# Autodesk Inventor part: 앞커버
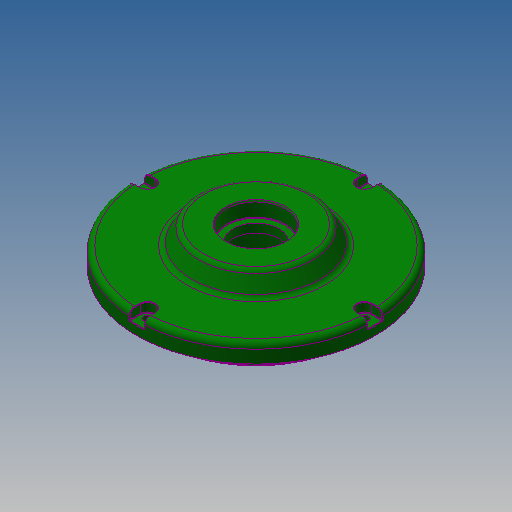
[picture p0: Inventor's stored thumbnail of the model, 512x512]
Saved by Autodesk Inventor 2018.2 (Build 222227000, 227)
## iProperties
Created: 2016-11
Part Number: 앞커버
Material: 알루미늄 6061
Document SubType Name: Modeling
Designer: mduedu
Density: 2.71 g/cm^3
Mass: 470.684 g
Surface Area: 413.208 cm^2
Volume: 173.684 cm^3
Appearance: 진녹색
Author: mduedu
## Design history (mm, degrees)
sketch "스케치1"
  geometry: L1 (30, -16)-(30, -30); L2 (30, -30)-(20, -35.774); L3 (20, -35.774)-(20, -65); L4 (20, -65)-(10, -65); L5 (10, -65)-(10, -53); L6 (10, -53)-(0, -53); L7 (0, -53)-(0, -23.5); L8 (0, 0)-(30, 0); L9 (14, -23.5)-(14, -20.5); L10 (14, -20.5)-(17, -20.5); L11 (17, -20.5)-(17, -12.5); L12 (0, -23.5)-(14, -23.5); L13 (21.7, -16)-(30, -16); L14 (21.7, -16)-(21.7, -12.5); L15 (21.7, -12.5)-(17, -12.5)
  constraints: 30 end point, 8 parallel, 5 perpendicular, 2 horizontal, 2 vertical alignment
  dimensions: "d0" = 10 distance of L5.end L6.end; "d2" = 10 distance of L3.end L4.end; "d3" = 10 distance between parallel lines of L1 L3; "d4" = 120 deg angle of L3 L2; "d6" = 60 diameter of L1.end L8; "d7" = 41 diameter of L10 L8; "d8" = 47 diameter of L12 L8; "d9" = 32 diameter of L13 L8; "d10" = 106 diameter of L6 L8; "d11" = 130 diameter of L4 L8; "d64" = 14 distance between parallel lines of L9 L7; "d65" = 3 distance of L9.end L10.end; "d66" = 8.3 distance of L13.start L1.start; "d67" = 25 diameter of L15 L8
revolve "회전1" sketch "스케치1" stored, may be unused: angle "d12" = 90 deg
fillet "모깎기1" dims "d13" = 1
fillet "모깎기2" dims "d14" = 3
chamfer "모따기1" distance "d15" = 1; stored, may be unused: second distance "d16" = 2, angle "d17" = 45 deg
fillet "모깎기3" dims "d18" = 0.3
chamfer "모따기2" distance "d36" = 0.8; stored, may be unused: second distance "d37" = 2, angle "d38" = 30 deg
sketch "스케치3"
  geometry: C1 r 65 at (0, 0) reference; A1 r 59 centre (0, 0) between (0, 59) and (59, 0); 2 further points
  constraints: 4 point on circle, 2 horizontal alignment, 2 vertical alignment, 1 centre point, 1 coincident
  dimensions: "d33" = 118 diameter of A1
sketch "스케치4"
  geometry: 4 further points
  constraints: 4 other
hole "구멍2" sketch "스케치4" at (0, 59), (-59, 0), (59, 0), (0, -59) diameter "d39" = 4.5; stored, may be unused: countersink angle "d43" = 90 deg, drill point angle "d45" = 0 deg; dims "d40" = 6, "d41" = 8, "d42" = 5, "d44" = 8
sketch "스케치6"
  geometry: L1 (-4, 5.877)-(-4, 0); L2 (4, 5.877)-(4, 0); A1 r 4 centre (0, 0) between (-2.712, 2.941) and (2.712, 2.941) reference; A2 r 65 centre (0, -59) between (-4, 5.877) and (4, 5.877) reference; 1 further point
  constraints: 4 end point, 4 point on circle, 2 tangent, 2 vertical
extrude "돌출2" cut sketch "스케치6" stored distance "d51" = 10; taper "d52" = 0 deg
fillet "모깎기5" dims "d56" = 0.3
fillet "모깎기6" dims "d57" = 0.3
sketch "스케치5"
  geometry: C1 r 30 at (0, 0); C2 r 47.5 at (0, 0); 1 further point
  constraints: 2 centre point, 2 coincident
  dimensions: "d46" = 60 diameter of C1; "d47" = 95 diameter of C2
extrude "돌출1" cut sketch "스케치5" distance "d48" = 10; taper "d49" = 0 deg
fillet "모깎기4" dims "d50" = 3
node "솔리드1"
pattern_circular "원형 패턴1" dims angle "d54" = 360 deg
pattern_circular "원형 패턴2" dims angle "d59" = 360 deg
pattern_circular "원형 패턴3" dims angle "d62" = 360 deg
